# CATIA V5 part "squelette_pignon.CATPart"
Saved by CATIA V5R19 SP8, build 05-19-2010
Part number: squelette_pignon
Publications: "Plan.1", "Esquisse.1", "Plan.2", "Point.2", "Point.3"
Bounding box of the stored display mesh (mm): x 27.851 to 43.851, y 0 to 340.099, z 0 to 136.954
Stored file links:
  G:\EU_thinkMotion\CFAO_2010\MMS_groupe3\MMS_groupe3\A reprendre\amenand\amenand\squelette_pignon.CATPart
  F:\thinkmotion CFAO v12.1\essuie_glace.CATProduct
  G:\EU_thinkMotion\CFAO_2010\MMS_groupe3\MMS_groupe3\A reprendre\amenand\amenand\squelette_coulisseau.CATPart
  G:\EU_thinkMotion\CFAO_2010\MMS_groupe3\MMS_groupe3\A reprendre\amenand\amenand\squelette_couronne.CATPart
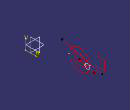
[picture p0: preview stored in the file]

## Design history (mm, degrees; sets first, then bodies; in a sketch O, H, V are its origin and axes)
Set1
  Plane1: linked copy from another document
  Point1: linked copy from another document
  Line1: linked copy from another document
  DatumCurve1: linked copy from another document
Set2 "set géométrique.10"
  Plane2: type Offset, RefPlane Plane1, Offset 36, reversed
  Line2: type PtDir, RefPoint Point1, Direction Line1, Support Plane1, Start 0, End 72
  Sketch1 on Plane1, origin (43.8512, 0, 0), H (0, 1, 0), V (0, 0, 1)
    circle A1 centre (288.0782, 78.8258) radius 11.25
    point P1 (288.0782, 78.8258)
    reference projected line E1 (321.5818, 69.9865) -> (251.964, 88.354) from Line2
    reference projected circle E2 centre (251.964, 88.354) radius 48.6 from edge of DatumCurve1
    radius A1 = 11.25
    coincidence: P1 E1
    tangency: A1 E2
  Point2: type Center, Curve Sketch1
  Point3: type OnCurve, Support Line2, RefPoint Point2, Length 34
Body1 (main body)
